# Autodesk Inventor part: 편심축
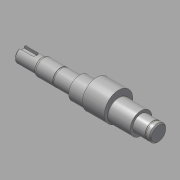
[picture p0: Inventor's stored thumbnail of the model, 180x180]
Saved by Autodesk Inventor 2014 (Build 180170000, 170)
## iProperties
Created: 2015-12
Part Number: 편심축
Material: 강철, 연강
Document SubType Name: Modeling
Designer: mduedu
Density: 7.86 g/cm^3
Appearance: 강철
Author: mduedu
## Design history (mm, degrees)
sketch "스케치1"
  geometry: L1 (-62.5, 0)-(62.5, 0); L2 (-62.5, 0)-(-62.5, 6.5); L3 (-62.5, 6.5)-(-43.5, 6.5); L4 (-43.5, 7)-(-42.634, 7.5); L5 (-42.634, 7.5)-(-9.5, 7.5); L6 (-9.5, 7.5)-(-9.5, 10); L7 (-9.5, 10)-(46.5, 10); L8 (46.5, 10)-(46.5, 7.5); L9 (46.5, 7.5)-(62.5, 7.5); L10 (62.5, 7.5)-(62.5, 0); L11 (-43.5, 6.5)-(-43.5, 7); 2 further points
  constraints: 22 end point, 6 parallel, 2 perpendicular, 1 coincident, 1 horizontal, 1 midpoint, 1 vertical
  dimensions: "d0" = 13 diameter of L3 L1; "d2" = 15 diameter of L5 L1; "d3" = 20 diameter of L7 L1; "d5" = 15 diameter of L9 L1; "d6" = 125 distance of L1.start L1.end; "d7" = 19 distance of L2.end L3.end; "d8" = 34 distance from line of L6 L3.end; "d9" = 56 distance of L6.end L7.end; "d41" = 14 diameter of L4.start L1; "d42" = 30 deg angle of L4 L3
revolve "회전1" sketch "스케치1" stored, may be unused: angle "d11" = 90 deg
node "작업 평면1"
sketch "스케치2"
  geometry: C1 r 13 at (0, 3); 1 further point
  constraints: 1 centre point, 1 vertical alignment
  dimensions: "d13" = 26 diameter of C1; "d14" = 3 distance of point (0, 0) C1.centre
extrude "돌출1" join sketch "스케치2" distance "d15" = 20; taper "d16" = 0 deg
node "작업 평면2"
sketch "스케치3"
  geometry: L1 (9.5, -2.5)-(-2.5, -2.5); L2 (-2.5, 2.5)-(9.5, 2.5); L3 (9.5, 2.5)-(9.5, -2.5); L4 (9.5, 6.5)-(9.5, -6.5) reference; A1 r 2.5 centre (-2.5, 0) between (-2.5, 2.5) and (-2.5, -2.5); 1 further point
  constraints: 6 end point, 2 point on circle, 2 tangent, 1 centre point, 1 collinear, 1 horizontal, 1 horizontal alignment, 1 parallel
  dimensions: "d17" = 5 distance of L2.end L1.start; "d19" = 12 distance from line of A1.centre L3
extrude "돌출2" cut sketch "스케치3" distance "d20" = 3; taper "d21" = 0 deg
chamfer "모따기1" distance "d22" = 1; stored, may be unused: second distance "d23" = 2, angle "d24" = 45 deg
fillet "모깎기1" dims "d25" = 3
sketch "스케치4"
  geometry: L1 (-9.5, -10)-(-9.5, 10) reference; L2 (-9.5, 0)-(0, 0); L3 (-26.65, 12.15)-(-25.5, 12.15); L4 (-25.5, 12.15)-(-25.5, 7.15); L5 (-25.5, 7.15)-(-26.65, 7.15); L6 (-26.65, 7.15)-(-26.65, 12.15); L7 (57.5, 12.15)-(58.65, 12.15); L8 (58.65, 12.15)-(58.65, 7.15); L9 (58.65, 7.15)-(57.5, 7.15); L10 (57.5, 7.15)-(57.5, 12.15); L11 (62.5, -7.5)-(62.5, 7.5) reference
  constraints: 18 end point, 4 parallel, 2 horizontal, 2 perpendicular, 1 midpoint
  dimensions: "d26" = 16 distance between parallel lines of L4 L1; "d27" = 1.15 distance of L3.start L3.end; "d28" = 14.3 diameter of L5 L2; "d29" = 5 distance of L3.end L4.end; "d30" = 1.15 distance of L7.start L7.end; "d31" = 5 distance of L7.end L8.end; "d32" = 5 distance between parallel lines of L10 L11; "d33" = 14.3 diameter of L9 L2
revolve "회전2" sketch "스케치4" stored, may be unused: angle "d34" = 90 deg
chamfer "모따기2" distance "d35" = 1; stored, may be unused: second distance "d36" = 2, angle "d37" = 45 deg
fillet "모깎기2" dims "d38" = 0.3
sketch "스케치5"
  geometry: 2 further points
  constraints: 1 coincident
sketch "스케치6"
  geometry: 1 further point
hole "구멍1" sketch "스케치6" at (2.5, -3.5) diameter "d43" = 4.917; stored, may be unused: countersink angle "d47" = 90 deg, drill point angle "d49" = 120 deg; dims "d44" = 14, "d45" = 4, "d46" = 2, "d48" = 17
node "솔리드1"
other parameters: "d12" = -15.5
